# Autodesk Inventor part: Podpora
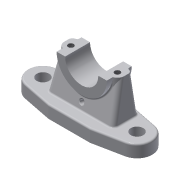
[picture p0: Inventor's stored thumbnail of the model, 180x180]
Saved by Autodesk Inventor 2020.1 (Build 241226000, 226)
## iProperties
Created: 2005-01
Part Number: Podpora
Document SubType Name: Modeling
Designer: F.Stasiak
Manufacturer: Standard
Standards Organization: Custom
Density: 1 g/cm^3
Material: Ogólny
Appearance: Biały
Manager: www.cadconsulting.pl
Company: Fabian Stasiak CAD Consulting
Author: F.Stasiak
Subject: Zbiór ćwiczeń. Autodesk Inventor 2020. Kurs podstawowy
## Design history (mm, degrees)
sketch "Szkic1"
  geometry: L1 (-75, 25)-(75, 25); L2 (75, 25)-(75, -25); L3 (75, -25)-(-75, -25); L4 (-75, -25)-(-75, 25); L5 (0, 25)-(0, -25); L6 (-75, 0)-(75, 0); 2 further points
  constraints: 12 end point, 5 midpoint, 2 parallel, 1 coincident, 1 horizontal, 1 perpendicular
  dimensions: "d0" = 150 distance of L2.end L3.end; "d1" = 50 distance of L3.end L1.start
extrude "Wyciągnięcie proste1" new body sketch "Szkic1" distance "d2" = 15; taper "d3" = 0 deg
sketch "Szkic2"
  geometry: L1 (75, 15)-(-75, 15) reference; L2 (-40, 15)-(-40, 60); L3 (-40, 60)-(0, 60); L4 (0, 60)-(40, 60); L5 (40, 60)-(40, 15); L6 (0, 60)-(0, 15); L7 (75, 0)-(-75, 0) reference
  constraints: 10 end point, 2 equal length, 2 parallel, 2 point on line, 1 midpoint, 1 vertical
  dimensions: "d4" = 60 distance between parallel lines of L7 L3; "d5" = 80 distance of L4.end L2.end; "d6" = 90 deg angle of L1 L2
extrude "Wyciągnięcie proste2" join sketch "Szkic2" distance "d7" = 20; taper "d8" = 0 deg
feature "Szkic powierzchni4" dims angle "d49" = 15 deg
feature "Szkic powierzchni5" dims angle "d53" = 5 deg
sketch "Szkic3"
  geometry: L1 (-40, 60)-(40, 60) reference; C1 r 20 at (0, 60)
  constraints: 2 midpoint, 1 centre point
  dimensions: "d9" = 40 diameter of C1
extrude "Wyciągnięcie proste3" cut sketch "Szkic3" extent not by distance; stored distance "d10" = 30; taper "d11" = 0 deg
sketch "Szkic4"
  geometry: L1 (40, 60)-(20, 60) reference; L2 (-20, 60)-(-40, 60) reference; L3 (-40, 60)-(-20, 60) reference; L4 (20, 60)-(40, 60) reference; A1 r 20 centre (0, 60) between (-20, 60) and (20, 60) reference; A2 r 30.239 centre (0, 60) between (-30.239, 60) and (30.239, 60)
  constraints: 2 point on circle, 2 point on line, 1 centre point
extrude "Wyciągnięcie proste4" join sketch "Szkic4" stored distance "d12" = 40; taper "d13" = 0 deg
chamfer "Faza5" distance "d50" = 10; stored, may be unused: second distance "d51" = 2, angle "d52" = 45 deg
chamfer "Faza6" distance "d54" = 10; stored, may be unused: second distance "d55" = 2, angle "d56" = 45 deg
chamfer "Faza1" distance "d21" = 50; stored, may be unused: second distance "d22" = 10, angle "d23" = 45 deg
chamfer "Faza2" distance "d24" = 50; stored, may be unused: second distance "d25" = 10, angle "d26" = 45 deg
chamfer "Faza3" distance "d27" = 50; stored, may be unused: second distance "d28" = 10, angle "d29" = 45 deg
chamfer "Faza4" distance "d30" = 50; stored, may be unused: second distance "d31" = 10, angle "d32" = 45 deg
sketch "Szkic6"
  geometry: L1 (25, 25)-(75, 15) reference; L2 (75, -15)-(25, -25) reference; L3 (75, 15)-(75, -15) reference; C1 r 18.297 at (56.703, 0)
  constraints: 3 tangent, 1 centre point
hole "Otwór2" sketch "Szkic6" at (56.703, 0) diameter "d33" = 15; stored, may be unused: countersink angle "d37" = 90 deg, drill point angle "d39" = 118 deg; dims "d34" = 6, "d35" = 4, "d36" = 2, "d38" = 15
sketch "Szkic8"
  geometry: L1 (-75, 15)-(-34.71, 23.058) reference; L2 (-75, -15)-(-75, 15) reference; L3 (-34.71, -23.058)-(-75, -15) reference; L4 (15.098, -25)-(-15.098, -25) reference; L5 (75, -15)-(34.71, -23.058) reference; L6 (75, 15)-(75, -15) reference; L7 (34.71, 23.058)-(75, 15) reference; L8 (-15.098, 25)-(15.098, 25) reference; L9 (38.406, 0)-(-40, 0) reference; A1 r 100 centre (-15.098, -75) between (-15.098, 25) and (-34.71, 23.058) reference; A2 r 100 centre (-15.098, 75) between (-34.71, -23.058) and (-15.098, -25) reference; A3 r 100 centre (15.098, 75) between (15.098, -25) and (34.71, -23.058) reference; A4 r 100 centre (15.098, -75) between (34.71, 23.058) and (15.098, 25) reference; A5 r 18.297 centre (56.703, 0) between (60.291, -17.942) and (60.291, 17.942); A6 r 26.986 centre (56.703, 0) between (38.585, 20) and (29.717, 0); 2 further points; 1 other entity
  constraints: 4 point on circle, 3 point on line, 3 tangent, 2 centre point, 2 other
extrude "Wyciągnięcie proste6" cut sketch "Szkic8" extent not by distance; stored distance "d44" = 50; taper "d45" = 0 deg
feature "Przesunięcie powierzchni1" dims "d69" = 10
sketch "Szkic10"
  geometry: L1 (-10.239, -10)-(-10.239, 20) reference; L2 (5.824, 0)-(5.824, 14.055) reference; L3 (-10.239, 5)-(5.824, 5); 1 further point
  constraints: 2 end point, 2 midpoint, 1 horizontal alignment, 1 perpendicular, 1 point on line, 2 other
extrude "Wyciągnięcie proste8" join sketch "Szkic10" stored distance "d70" = 10; taper "d71" = 0 deg
hole "Otwór4" diameter "d74" = 6.647; stored, may be unused: countersink angle "d78" = 90 deg, drill point angle "d80" = 118 deg; dims "d72" = 10, "d73" = 10, "d75" = 6, "d76" = 4, "d77" = 2, "d79" = 15
mirror "Lustro3"
fillet "Zaokrąglenie2" dims "d81" = 5
fillet "Zaokrąglenie4" dims "d83" = 2
fillet "Zaokrąglenie5" dims "d84" = 2
fillet "Zaokrąglenie6" dims "d85" = 2
fillet "Zaokrąglenie7" dims "d86" = 2
fillet "Zaokrąglenie8" dims "d87" = 2
sketch "Szkic11"
  geometry: L1 (34.964, 42.465)-(34.964, 6.465); 2 further points; 1 other entity
  constraints: 2 end point, 1 vertical, 1 other
  dimensions: "d88" = 36 distance of L1.start L1.end
hole "Otwór5" sketch "Szkic11" at (34.964, 6.465) diameter "d89" = 5; stored, may be unused: countersink angle "d93" = 120 deg, drill point angle "d95" = 118 deg; dims "d90" = 6, "d91" = 7, "d92" = 2, "d94" = 15
node "Bryła1"
node "Korpusy bryłowe"
node "Korpusy powierzchniowe"
